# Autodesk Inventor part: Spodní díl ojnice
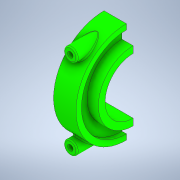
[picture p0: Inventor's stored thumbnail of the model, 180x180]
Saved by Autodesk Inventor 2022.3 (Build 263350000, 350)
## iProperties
Created: 2025-11
Part Number: Spodní díl ojnice
Material: Všeobecné
Description: STEP AP203
Document SubType Name: Modeling
Designer: Hra42
Density: 1 g/cm^3
Appearance: Výchozí
Title: Spodní díl ojnice.STEP
Revision Number: LIBOVOLNÃ
Sending System: SolidWorks 2024
Preprocessor: SwSTEP 2.0
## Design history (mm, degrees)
feature "Spodní díl ojnice.ipt_1_"
node "Těleso1"
